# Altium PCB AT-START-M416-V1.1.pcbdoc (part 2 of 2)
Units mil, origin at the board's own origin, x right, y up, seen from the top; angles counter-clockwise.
Board outline 4292.45 x 3617.4 mil, 2 copper layers (Top Layer, Bottom Layer); 119 components, 108 nets, 464 pads, 671 vias.
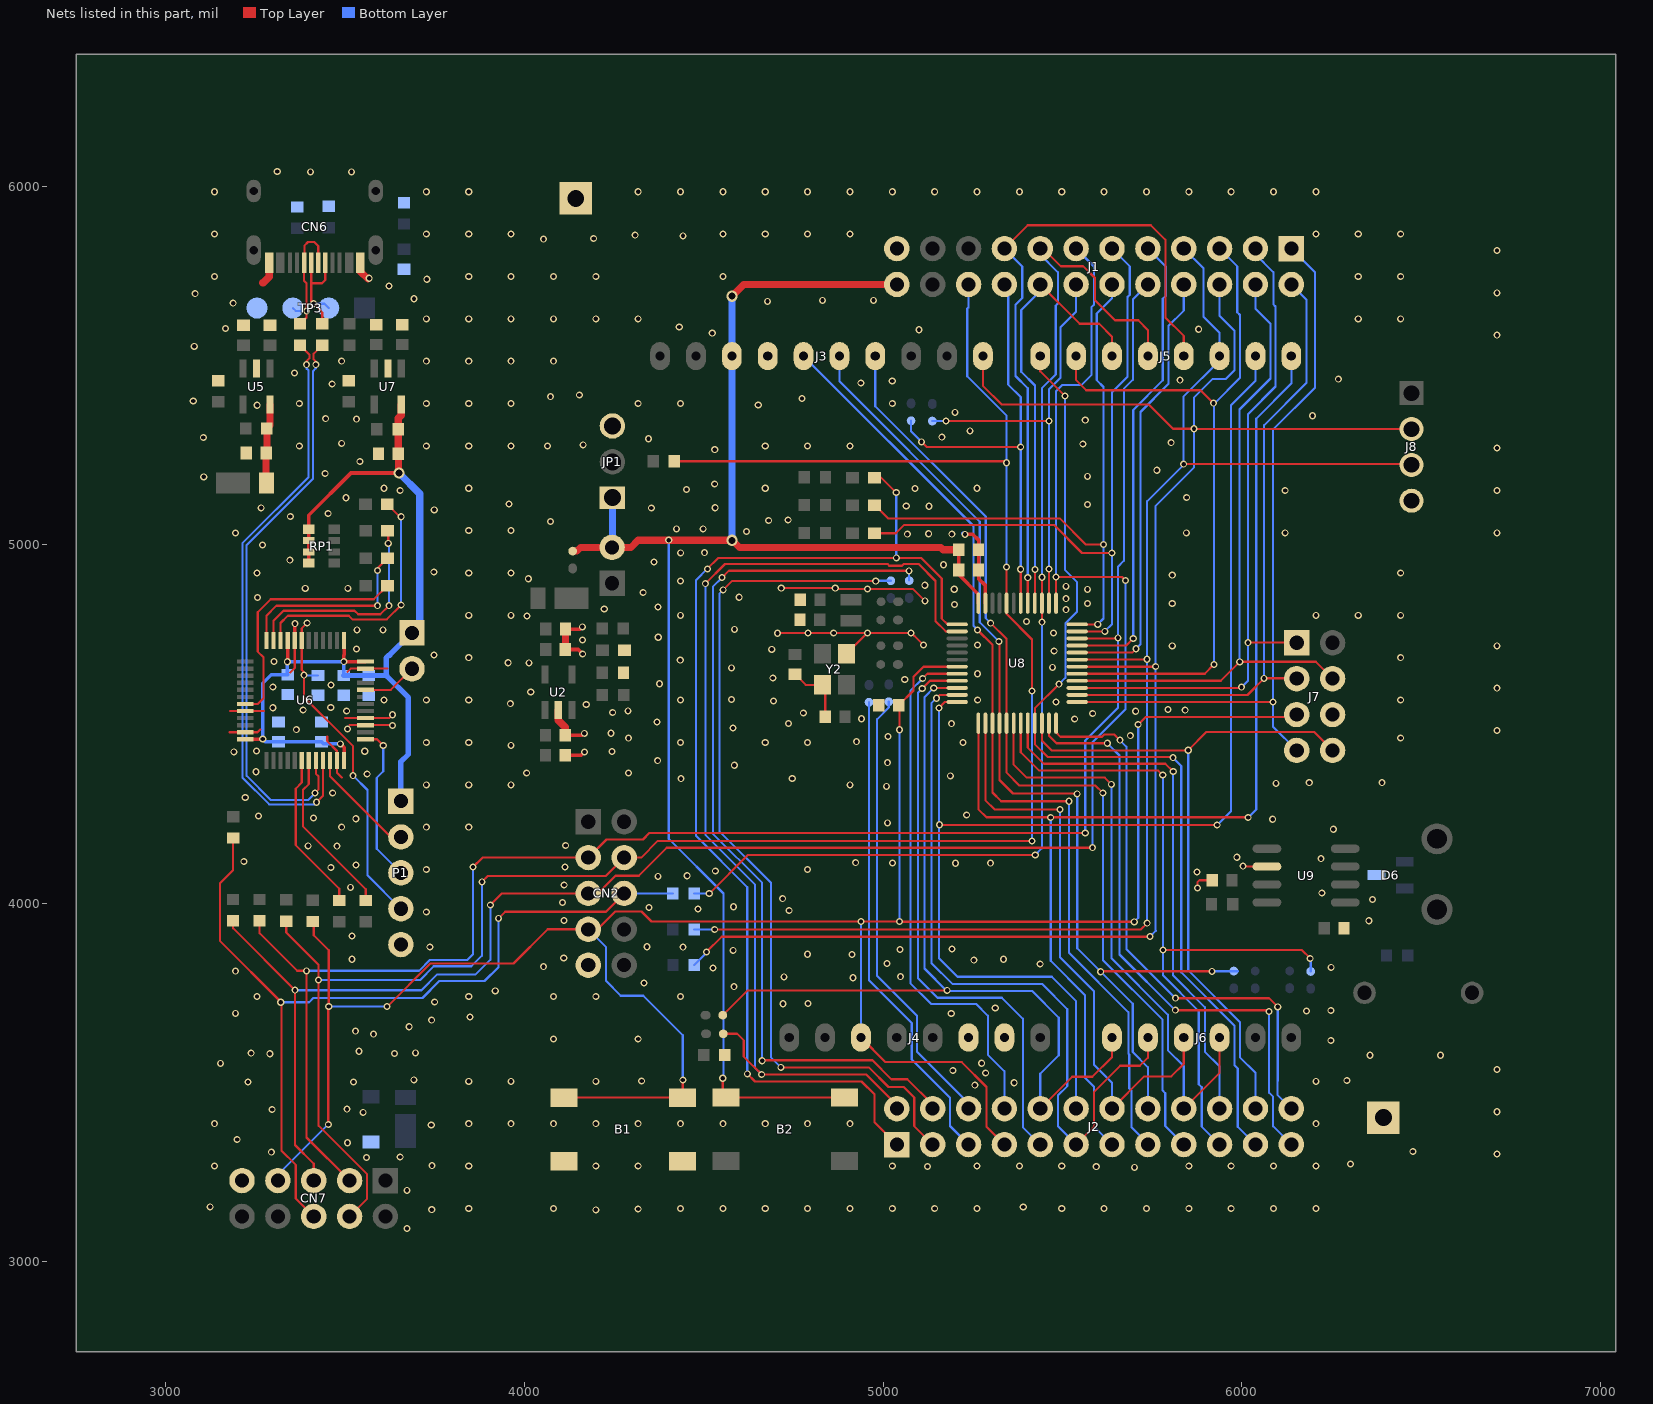
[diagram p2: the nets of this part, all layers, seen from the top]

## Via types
v1: diameter 19.68, hole 11.81, Top Layer to Bottom Layer, 317 vias
v2: diameter 19.7, hole 11.81, Top Layer to Bottom Layer, 224 vias
v3: diameter 19.7, hole 11.8, Top Layer to Bottom Layer, 111 vias
v4: diameter 31.5, hole 19.68, Top Layer to Bottom Layer, 19 vias

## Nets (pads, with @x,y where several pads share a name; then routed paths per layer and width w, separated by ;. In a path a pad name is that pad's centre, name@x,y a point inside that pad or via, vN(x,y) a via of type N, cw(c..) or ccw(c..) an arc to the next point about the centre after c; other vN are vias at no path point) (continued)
GND: B1.3 B1.4 C1.1 C2.1 C3.1 C4.1 C5.1 C6.1 C7.1 C8.1 C9.1 C10.1 C11.1 C12.1 C13.1 C14.1 C15.1 C16.1 C17.1 C18.1 C19.1 C20.1 C21.1 C22.1 C23.2 C24.2 C25.2 C26.2 CN2.9 CN6.A1B12 CN6.B1A12 CN7.9 D4.2 D6.3 J1.23 J3.7 J4.6 J4.7 J7.6 J8.4 JP1.3 LED1.2 P1.5 R2.2 R20.2 R34.2 R35.2 R36.2 R49.2 R51.2 T1.1 T2.1 TP3.4 U2.2 U5.2 U6.8 U6.20 U6.23 U6.35 U6.39 U6.40 U6.47 U7.2 U8.47 U9.2 Y2.2 Y2.4 | length 2758.9
  Top Layer w6: 3177.08,4477.12 U6.23@3221.25,4477.12 3255.17,4477.12 3262.81,4484.75 ; 3178.66,4536.18 U6.20@3221.25,4536.18 3273.47,4536.18 ; 3346.33,4643.65 3359.04,4656.36 U6.8@3359.04,4733.03 ; 3449.63,4465.2 3449.63,4452.3 3477.16,4424.78 U6.35@3477.16,4398.38 3477.16,4363.64 3490.18,4350.62 ; 3500.02,4516.49 U6.40@3555.9,4516.49 3622.6,4516.49 v1(3631.92,4525.82) ; 3506.46,4645.8 3514.94,4654.29 U6.47@3555.9,4654.29 3617.03,4654.29 ; 3512.29,4496.81 U6.39@3555.9,4496.81 3630.94,4496.81 v2(3631.92,4495.82) ; v3(4705.25,4753.04) 4705.97,4753.76 v3(4790.18,4753.76) v3(4861.89,4753.76) v2@4955.4,4753.76 ; v3(4715.75,4878.79) v3(4866.25,4878.79) 4868.88,4876.16 v3(4956.33,4876.16) 5083.47,4876.16 v3(5116.22,4843.4) ; C3.1@4753.97,4638.93 4783.72,4609.18 Y2.4@4830.51,4609.18 4838.41,4601.27 C4.1@4838.41,4520.49 ; Y2.2@4897.44,4695.8 v2@4955.4,4753.76 ; v3(5112.65,4719.92) 5086.5,4746.07 5086.5,4746.49 5079.23,4753.76 v3(5077.77,4753.76) v2(4956.43,4753.76) v2@4955.4,4753.76 ; v3(5875.97,4042.49) 5875.97,4058.49 5881.97,4064.49 C13.1@5917.41,4064.49 ; v3(6002.97,4103.49) 6003.97,4102.49 U9.2@6069.82,4102.49
  Top Layer w10: U6.8@3359.04,4733.03 3359.04,4778.94 v2(3359.92,4779.82) ; C23.2@4113.53,4412.49 4157.32,4412.49 v3(4167.06,4422.23) ; C24.2@4113.53,4468.49 4161.11,4468.49 v3(4166.69,4474.06) ; C25.2@4113.81,4707.66 4149.5,4707.66 v3(4162.07,4695.08) ; C26.2@4114.14,4764.74 4154.85,4764.74 v1(4161.02,4770.91) ; v1(5227.81,5028.9) 5249.82,5028.9 5265.85,5012.87 C6.1@5265.85,4985.83 C7.1@5265.85,4929.3 ; C7.1@5265.91,4929.24 5265.91,4905.39 5284.94,4886.36 U8.47@5284.94,4836.89
  Top Layer w20: 3269.89,5730.23 3271.47,5730.23 3288.12,5746.88 CN6.B1A12@3288.12,5785.52 ; CN6.A1B12@3541.92,5785.52 3541.92,5761.94 v2@3563.18,5740.69 ; U2.2@4094,4538.45 4094,4510.46 4113.53,4490.93 C24.2@4113.53,4468.49 ; C25.2@4113.81,4707.66 4114.14,4707.99 C26.2@4114.14,4764.74
  Bottom Layer w10: v1@5221.26,5032.4 5224.76,5028.9 v1(5227.81,5028.9)
  other v1: 4198.61,3145.4 3741.26,3145.84 4316.72,3147.4 3844.28,3149.4 4080.5,3149.4 4434.83,3149.4 4552.94,3149.4 4671.05,3149.4 4789.16,3149.4 4907.27,3149.4 5025.38,3149.4 5143.49,3149.4 5261.6,3149.4 5497.82,3149.4 5615.93,3149.4 5734.04,3149.4 5852.15,3149.4 5970.26,3149.4 6088.37,3149.4 6206.48,3149.4 5390.37,3152.95 3123.38,3153.74 5700.88,3263.95 5123.75,3265.93 5594.02,3265.73 3135.61,3267.51 3742.15,3268.39 3844.28,3267.51 4198.61,3267.51 4316.72,3267.51 5025.38,3267.51 5261.6,3267.51 5379.71,3267.51 5497.82,3267.51 5852.15,3267.51 5970.26,3267.51 6088.37,3267.51 6206.48,3267.51 6302.59,3273.51 6711.39,3300.71 6476.7,3307.73 3739.85,3381.93 3135.61,3385.62 3844.28,3385.62 3962.39,3385.62 4080.5,3385.62 4198.61,3385.62 4316.72,3385.62 4434.83,3385.62 4552.94,3385.62 4671.05,3385.62 4789.16,3385.62 4907.27,3385.62 6206.48,3385.62 6711.39,3418.82 3844.28,3503.73 3962.39,3503.73 4198.61,3503.73 6206.48,3503.73 4326.58,3504.52 6292.62,3505.7 6711.39,3536.93 4080.5,3621.84 4316.72,3621.84 3253.72,3739.95 3844.28,3739.95 4080.5,3739.95 4198.61,3739.95 4434.83,3739.95 5252.72,3841.48 4913.27,3857.06 4789.16,3858.06 3726.16,3976.17 4719.54,4012.9 3726.16,4094.28 4789.16,4094.28 5201.36,4111.78 4923.27,4113.28 3489.94,4212.39 3726.16,4212.39 3844.28,4212.39 3726.16,4330.5 3844.28,4330.5 3962.39,4330.5 4907.27,4330.5 4005.84,4363.65 3962.39,4440.61 3726.16,4448.61 3844.28,4448.61 4434.83,4448.61 4671.05,4448.61 4789.16,4448.61 4925.27,4450.61 6442.7,4461.04 6711.39,4481.81 4939.27,4514.72 4777.16,4530.72 3960.39,4556.72 4694.14,4564.35 3608.05,4566.72 3726.16,4566.72 3844.28,4566.72 4434.83,4566.72 5263.37,4566.72 6442.7,4566.72 4017.17,4589.47 6711.39,4599.92 3954.39,4670.83 4012.13,4670.54 4434.04,4677.99 3844.28,4684.83 6442.7,4684.83 4689.2,4708.25 6711.39,4718.03 5262.78,4720.35 4006.5,4800.94 3844.28,4802.94 3962.39,4802.94 4434.83,4802.94 6206.48,4802.94 6324.59,4802.94 6442.7,4802.94 4330.8,4867 4434.83,4899.05 4010.44,4904.91 3253.72,4921.05 3844.28,4921.05 3962.39,4921.05 6442.7,4921.05 6711.39,5032.99 3844.28,5039.16 3962.39,5039.16 4072.21,5064.82 4353.46,5102.01 4531.49,5103.04 3956.39,5113.27 6711.39,5151.1 3608.05,5157.27 3844.28,5157.27 4671.05,5157.27 5261.6,5157.27 4530.18,5169.4 4530.3,5264.94 6711.39,5269.21 3371.83,5275.38 3726.16,5275.38 3844.28,5275.38 3962.39,5275.38 4063.76,5275.38 4671.05,5275.38 4789.16,5275.38 4907.27,5275.38 4163.35,5278.35 3489.94,5282.48 4345.54,5295.42 3254.32,5388.75 4651.51,5389.35 3371.83,5393.49 3726.16,5393.49 3844.28,5393.49 3962.39,5393.49 4316.72,5393.49 4434.83,5393.49 5025.38,5393.49 4773.37,5407.31 4072.3,5412.62 4152.61,5417.49 3489.94,5511.6 3726.16,5511.6 3844.28,5511.6 3962.39,5511.6 4080.5,5511.6 6711.39,5584.17 5879.58,5600.63 3726.16,5629.71 3844.28,5629.71 3962.39,5629.71 4080.5,5629.71 4198.61,5629.71 4316.72,5629.71 6324.59,5629.71 6442.7,5629.71 6711.39,5702.28 3621.67,5721.18 3727.35,5740.12 3135.61,5747.82 3844.28,5747.82 3962.39,5747.82 4080.5,5747.82 4198.61,5747.82 4552.94,5747.82 6324.59,5747.82 6442.7,5747.82 6711.39,5820.39 4052.5,5851.93 4192.61,5853.93 4441.93,5861.19 4308.43,5862.97 3135.61,5865.93 3726.16,5865.93 3844.28,5865.93 3962.39,5865.93 4552.94,5865.93 4671.05,5865.93 4789.16,5865.93 4907.27,5865.93 6206.48,5865.93 6324.59,5865.93 6442.7,5865.93 3135.61,5984.04 3726.16,5984.04 3844.28,5984.04 4316.72,5984.04 4434.83,5984.04 4552.94,5984.04 4671.05,5984.04 4789.16,5984.04 4907.27,5984.04 5025.38,5984.04 5143.49,5984.04 5261.6,5984.04 5379.71,5984.04 5497.82,5984.04 5615.93,5984.04 5734.04,5984.04 5852.15,5984.04 5970.26,5984.04 6088.37,5984.04 6206.48,5984.04 3310.43,6040.29
  other v2: 3672.2,3093.06 3672.47,3199.71 3559.16,3291.61 3653.25,3292.5 3294,3306.17 3506.02,3332.5 3198.63,3341.75 3549.87,3417.35 3296.17,3424.98 3504.98,3426.15 5255.54,3492.87 5365.15,3499.68 3228.92,3501.56 3522.79,3502.15 3691.11,3507.76 5285.68,3526.79 5194.13,3533.53 3152.29,3553.86 5274.63,3554.03 3289.67,3580.56 3637.43,3581.44 3237.63,3582.27 3695.65,3583.12 3538.06,3587.46 3579,3635.21 3528.58,3643.52 3678.17,3655.78 3740.98,3674.21 3847.64,3682.95 3193.72,3693.28 5189.63,3693.14 6180.37,3699.72 5312.46,3708.2 4720.65,3720.04 4790.52,3720.83 3749.27,3724.53 3918.19,3755.95 4583.61,3767.53 4333.11,3777.55 4915.63,3792.43 4723.47,3794.94 5048.18,3795.59 3193.72,3810.91 4525.54,3819.39 4052.83,3823.31 5437.72,3831.13 5010.5,3831.88 3518.6,3843.99 5335.62,3844.03 4109.25,3847.81 4581.64,3868.98 5046.99,3871.38 5192.13,3872.51 3735.9,3878.03 4441.86,3877.81 4341.2,3878.99 3518.6,3908.73 4110.1,3952.22 4737.82,3979.9 4483.25,3984.34 4346.94,3988.33 4582.48,3990.46 4105.76,4002.54 3514.75,4044.56 4110.5,4051.1 4371.83,4075.17 4453.27,4076.83 3459.69,4100.22 4112.47,4101.49 3530.14,4106.73 5298.87,4111.95 5025.57,4112.54 3217.09,4116.59 3476.86,4159.43 3396.66,4160.28 4114.58,4161.55 5012.13,4224.55 3529.45,4235.76 3411.13,4237.59 3258.15,4243.3 5232.69,4246.05 3221.2,4294.8 3464.92,4307.4 5009.17,4326.33 4436.21,4347.54 4746.34,4348.33 5187.1,4355.59 3561.25,4360.89 4290.08,4363.66 3250.89,4366.78 4584.77,4384.96 5012.13,4392.23 4371.1,4397.79 3189.36,4422.53 4243.9,4423.16 3252.21,4424.41 3554.4,4424.05 5222.78,4448.25 4290.08,4460.46 5013.36,4465.06 4240.99,4474.13 3363.6,4484.14 3506.08,4485.92 4580.92,4488.88 4736.02,4501.09 5190.21,4500.95 4368.88,4505.26 5533.86,4514.14 4245.68,4532.4 3503.93,4536.25 4288.31,4536.84 3382.58,4538.96 3297.98,4545.23 3459.5,4545.96 5481.39,4561.32 4577.32,4568.11 3297.98,4602.86 3460.17,4608.96 5060.02,4624.06 4692.19,4628.23 5262.89,4640.19 4577.32,4656.53 5471.9,4658.08 3301.33,4674.5 3747.34,4692.23 5476.62,4703.31 3531.17,4708.99 5475.08,4753.94 3532.55,4762.54 3605.58,4762.54 4585.36,4763.88 5399.37,4785.55 5509.36,4818.8 4372.15,4826.17 5509.36,4849.33 3255.26,4853.03 4598.39,4853.48 3388.48,4878.29 3507.29,4878.29 5509.36,4883.96 5116,4886.84 3746.99,4923.79 4360.86,4951.45 3345.43,4956.68 4435.35,4977.17 4501.58,4977.61 3269.05,4998.99 5067.13,5029.27 5191.32,5029.18 5126.72,5030.39 3193.78,5032.65 4680.74,5067.25 4734.94,5069.09 3346.84,5078.63 3452.5,5086.71 3748.16,5097.17 3265.53,5102.71 5127.86,5107.09 5064.31,5107.88 3501.75,5130.86 3653.09,5151.06 5088.78,5156.83 3105.54,5189.16 3444.04,5198.34 3540.75,5231.89 5556.58,5280.86 3104.35,5298.69 5163.46,5299.75 5241.76,5317.4 5563.37,5347.09 3531.67,5349.91 3445.37,5351.39 5200.15,5369.08 3076.24,5400.27 3463.63,5447.81 4937.6,5451.15 5025.23,5456.48 5827.27,5458.64 3358.24,5478.4 3079,5553.13 4523.34,5589.82 5099.47,5599.34 3166.21,5602.49 4431.37,5606.79 3187.53,5673.41 4677.34,5678.58 4830.99,5681.25 4973.09,5681.25 3692.06,5685.72 3081.44,5699.89 3566.6,5742.92 3403.39,6039.7 3517.08,6039.7
  other v3: 6357.06,3576.3 6553.91,3576.3 6247.97,3617.49 6247.97,3701.49 6248.97,3821.49 6353.97,3951.49 6363.97,4010.49 6222.97,4028.49 5874.97,4087.49 4531.97,4090.49 6220.97,4124.49 5985.97,4128.49 6254.97,4206.49 6085.97,4234.49 6094.97,4334.49 6187.97,4336.49 6390.97,4336.49 5688.97,4467.49 5583.97,4529.49 5703.97,4535.49 5841.97,4538.49 5793.97,4540.49 4171.97,4554.49 4376.06,4612.31 5805.88,4718.03 4161.47,4734.22 4372.65,4741.91 4222.15,4820.86 5198.71,4833.39 5569.66,4836.14 5805.88,4836.14 5198.1,4875.69 5569.66,4875.51 5805.88,4914.88 5167.89,4943.97 5845.25,5032.99 6120.84,5032.99 4619.09,5036.42 4423.91,5044.31 4498.08,5044.31 5569.66,5111.73 5846.11,5131.39 6120.84,5151.1 4451.46,5153.83 5569.66,5190.47 5762.97,5207.49 5802.97,5284.49 6196.97,5359.49 6268.97,5461.49
LD1: LD1.2 U6.10 | length 713.3
  Top Layer w6: U6.10@3319.67,4733.03 3319.67,4781.57 3339.92,4801.82 3509.92,4801.82 3519.92,4791.82 3615.92,4791.82 v1(3655.92,4831.82) ; LD1.2@3617.1,5113.03 3652.31,5077.82 v1(3655.92,5077.82)
  Bottom Layer w6: v1(3655.92,4831.82) v1(3655.92,5077.82)
LD2: LD2.2 U6.11 | length 613.2
  Top Layer w6: U6.11@3299.99,4733.03 3299.99,4787.88 3327.92,4815.82 3525.92,4815.82 3535.92,4805.82 3597.92,4805.82 v1(3621.92,4829.82) ; LD2.2@3618.06,5038.93 3619.92,5037.06 v1(3619.92,5003.82)
  Bottom Layer w6: v1(3619.92,5003.82) 3621.92,5001.82 v1(3621.92,4829.82)
LD3: LD3.2 U6.12 | length 534.1
  Top Layer w6: U6.12@3280.3,4733.03 3280.3,4802.2 3307.92,4829.82 v1(3589.92,4829.82) ; v1(3589.92,4927.82) 3589.92,4933.85 LD3.2@3618.1,4962.03
  Bottom Layer w6: v1(3589.92,4829.82) v1(3589.92,4927.82)
LD4: LD4.2 U6.19 | length 696.8
  Top Layer w6: U6.19@3221.25,4555.86 3255.97,4555.86 3271.92,4571.82 3271.92,4685.82 3255.92,4701.82 3255.92,4811.82 3291.92,4847.82 3579.85,4847.82 LD4.2@3618.06,4886.03
M-ATLK_RX: R48.1 U6.31 | length 470.7
  Top Layer w6: U6.31@3398.41,4398.38 3398.41,4332.34 3381.92,4315.85 3381.92,4214.86 3557.1,4039.68 R48.1@3557.1,4007.03
M-ATLK_TX: R47.1 U6.30 | length 448.5
  Top Layer w6: U6.30@3378.73,4398.38 3378.73,4336.66 3361.92,4319.85 3361.92,4162.2 3483.1,4041.03 R47.1@3483.1,4007.03
M-BOOT0: J9.2 U6.44 | length 154.6
  Top Layer w6: U6.44@3555.9,4595.23 3627.3,4595.23 J9.2@3686.1,4654.03
M-NRST: C22.2 P1.4 U6.7 | length 957
  Top Layer w6: v1(3393.92,4781.82) 3378.73,4766.62 U6.7@3378.73,4733.03 3378.73,4651.01 3384.73,4645.01 3384.73,4575.37 3521.92,4438.17 v1(3521.92,4355.82)
  Bottom Layer w6: v2(3384.73,4636.07) 3385.42,4635.38 C22.2@3423.92,4635.38 ; v1(3521.92,4355.82) 3561.92,4315.82 3561.92,4078.2 P1.4@3655.1,3985.03
M-SWCLK: P1.3 U6.37 | length 447.4
  Top Layer w6: U6.37@3555.9,4457.43 3588.31,4457.43 v1(3605.92,4439.82)
  Bottom Layer w6: v1(3605.92,4439.82) 3605.92,4367.82 3587.92,4349.82 3587.92,4152.2 P1.3@3655.1,4085.03
M-SWDIO: P1.2 U6.34 | length 311.8
  Top Layer w6: U6.34@3457.47,4398.38 3457.47,4354.27 3626.72,4185.03 P1.2@3655.1,4185.03
M-USB_DM: R38.2 U6.32 | length 1617.9
  Top Layer w6: v2(3415.92,4307.82) 3425.78,4317.68 3425.78,4353.69 3418.1,4361.38 U6.32@3418.1,4398.38 ; v2(3417.92,5501.82) 3417.92,5510.87 3411.92,5516.87 3411.92,5532.16 R38.2@3435.92,5556.16
  Bottom Layer w6: v2(3415.92,4307.82) 3395.92,4287.82 3292.9,4287.82 3225.1,4355.61 3225.1,4998.99 3409.92,5183.82 3409.92,5483.82 3417.92,5491.82 v2(3417.92,5501.82)
M-USB_DP: R37.2 U6.33 | length 1662.9
  Top Layer w6: R37.2@3373.92,5556.16 3399.92,5530.16 3399.92,5519.55 3391.92,5511.55 v1(3391.92,5501.82) ; v2(3419.92,4281.82) 3437.78,4299.68 U6.33@3437.78,4398.38
  Bottom Layer w6: v1(3391.92,5501.82) 3391.92,5491.42 3397.92,5485.42 3397.92,5188.79 3213.1,5003.96 3213.1,4350.64 3287.92,4275.82 3413.92,4275.82 v2(3419.92,4281.82)
NRST/PF2: B1.1 B1.2 C5.2 CN2.7 CN7.7 J2.7 J4.3 J7.5 R46.2 U8.7 | length 6865.4
  Top Layer w6: R46.2@3409.1,3947.03 3412.1,3944.03 3412.1,3911.15 3453.92,3869.33 v2(3453.92,3712.19) 3452.74,3711.01 v2(3452.74,3383.56) ; v1(3616.76,3711.99) 3737.05,3832.28 3969.28,3832.28 4064.53,3927.53 CN2.7@4177.67,3927.53 4203.13,3927.53 4252.77,3977.17 4326.06,3977.17 4353.93,3949.29 v1@4938.05,3949.29 ; B1.1@4110.01,3458.22 B1.2@4440.71,3458.22 4441.21,3458.72 v3(4441.21,3507.15) ; J4.3@4937.93,3625.82 5006.53,3557.21 5218.78,3557.21 5287.94,3488.05 5287.94,3377.38 J2.7@5337.93,3327.39 ; v1(4937.93,3949.17) v1@4938.05,3949.29 ; v3(5045.56,4484.05) 5045.56,4549.51 C5.2@5043.05,4552.03 5084.66,4593.63 5084.66,4632.06 5112.4,4659.79 U8.7@5206.24,4659.79 ; v3(5699.97,3948.49) 5046.42,3948.49 v3(5045.61,3949.29) v1@4938.05,3949.29 ; v3(5710.97,4498.49) 5731.97,4519.49 6146.02,4519.49 J7.5@6152.93,4526.39
  Bottom Layer w6: CN7.7@3312.1,3227.03 3312.1,3242.91 v2(3452.74,3383.56) ; v2(3453.92,3712.19) 3616.56,3712.19 v1(3616.76,3711.99) ; CN2.7@4177.67,3927.53 4227.41,3877.79 4227.41,3783.2 4268.13,3742.48 4330.94,3742.48 4441.21,3632.2 v3(4441.21,3507.15) ; J4.3@4937.93,3625.82 v1(4937.93,3949.17) ; v3(5045.61,3949.29) v3(5045.56,4484.05) ; v3(5699.97,3948.49) 5710.97,3959.49 v3(5710.97,4498.49)
PA0: J2.10 J6.1 R18.1 U8.10 | length 2535.9
  Top Layer w6: R18.1@4552.67,3688.08 4621.93,3757.34 v3(5178.41,3757.34) ; v1(5140.91,4600.69) U8.10@5206.24,4600.69 ; J2.10@5437.93,3427.39 5526.91,3516.37 5583.1,3516.37 5637.93,3571.19 J6.1@5637.93,3625.82
  Bottom Layer w6: v1(5140.91,4600.69) 5114.9,4574.68 5114.9,3818.16 5178.05,3755.01 v3@5178.41,3755.38 ; v3(5178.41,3757.34) v3@5178.41,3755.38 ; J2.10@5437.93,3427.39 5437.93,3524.74 5489.42,3576.23 5489.42,3681.18 5415.22,3755.38 v3@5178.41,3755.38
PA1: J2.11 J6.2 U8.11 | length 2060.1
  Top Layer w6: v1(5148.24,4571.84) 5157.39,4580.99 U8.11@5206.24,4580.99 ; J2.11@5537.93,3327.39 5587.23,3376.7 5587.23,3473.4 5660.76,3546.92 5715.38,3546.92 5737.93,3569.46 J6.2@5737.93,3625.82
  Bottom Layer w6: v1(5148.24,4571.84) 5134.38,4557.98 5134.38,3833.78 5192.69,3775.48 5442.56,3775.48 5513.01,3705.02 5513.01,3490.3 5487.21,3464.5 5487.21,3378.11 J2.11@5537.93,3327.39
PA2: J2.12 J5.2 U8.12 | length 3617.3
  Top Layer w6: v1(5155.54,4544.83) 5172,4561.29 U8.12@5206.24,4561.29 ; v1(5156.64,4219.06) 5157.26,4218.43 v1(5931.14,4218.43)
  Bottom Layer w6: v1(5155.54,4544.83) v1@5155.54,4216.06 ; v1(5156.64,4219.06) 5156.64,4217.16 v1@5155.54,4216.06 ; J2.12@5537.93,3427.39 5537.93,3727.28 5470.06,3795.15 5207.02,3795.15 5155.54,3846.64 v1@5155.54,4216.06 ; v1(5931.14,4218.43) 5970.01,4257.3 5970.01,5389.55 6037.93,5457.47 J5.2@6037.93,5525.82
PA3: J2.13 J5.1 U8.13 | length 3322.2
  Top Layer w6: U8.13@5265.24,4502.29 5265.24,4262.51 5287.79,4239.96 5467.18,4239.96 5466.97,4239.76 v3(5466.97,4239.49) 5467.45,4239.96 6016.73,4239.96 v1(6017.57,4239.12)
  Bottom Layer w6: v3(5466.97,4239.49) 5466.97,3839.49 5562.47,3743.99 5562.47,3513.58 5588.15,3487.9 5588.15,3377.18 J2.13@5637.93,3327.39 ; v1(6017.57,4239.12) 6040.14,4261.69 6040.14,5351.42 6137.93,5449.2 J5.1@6137.93,5525.82
PA4: J2.14 J6.3 U8.14 | length 1653.3
  Top Layer w6: U8.14@5284.94,4502.29 5284.94,4287.26 5310.73,4261.47 v3(5492.97,4261.49) ; J2.14@5637.93,3427.39 5727.92,3517.39 5803.28,3517.39 5837.93,3552.03 J6.3@5837.93,3625.82
  Bottom Layer w6: v3(5492.97,4261.49) 5492.97,3849.49 5587.68,3754.78 5587.68,3549.98 5637.93,3499.74 J2.14@5637.93,3427.39
PA5: J2.15 J3.6 U8.15 | length 2706.5
  Top Layer w6: v1(5262.99,4762.21) 5304.64,4720.55 U8.15@5304.64,4502.29 5304.64,4309.03 5329.11,4284.57 v1(5517.68,4284.57)
  Bottom Layer w6: J3.6@4777.93,5525.82 5251.54,5052.21 5251.54,4773.66 v1(5262.99,4762.21) ; v1(5517.68,4284.57) 5517.97,4284.27 5517.97,3861.78 5683.62,3696.13 5683.62,3580.61 5686.12,3578.1 5686.12,3483.5 5692.43,3477.2 5692.43,3375.89 5737.93,3330.39 J2.15@5737.93,3327.39
PA6: J2.16 J3.5 R25.1 U8.16 | length 2941.9
  Top Layer w6: v1(5322.25,4730.35) 5324.34,4728.26 U8.16@5324.34,4502.29 5324.34,4343.73 5361.93,4306.14 5540.09,4306.14 v1(5540.82,4305.41) ; v3(5606.26,3809.24) 5607.43,3810.42 v3(5916.99,3810.42)
  Bottom Layer w6: J3.5@4877.93,5525.82 4877.93,5455.38 5268.99,5064.32 5268.99,4783.61 v1(5322.25,4730.35) ; v1(5540.82,4305.41) 5540.82,3874.69 v3(5606.26,3809.24) 5695.62,3719.89 5695.62,3585.58 5737.93,3543.27 J2.16@5737.93,3427.39 ; v3(5916.99,3810.42) 5988.44,3810.42 R25.1@5988.61,3810.24
PA7: J2.17 J3.4 U8.17 | length 2678.8
  Top Layer w6: v1(5299.64,4781.17) 5344.04,4736.77 U8.17@5344.04,4502.29 5344.04,4364.42 5379.71,4328.75 5591.63,4328.75 v1(5612.44,4307.94)
  Bottom Layer w6: J3.4@4977.93,5525.82 4977.93,5386.12 5285.71,5078.34 5285.71,4795.1 v1(5299.64,4781.17) ; v1(5612.44,4307.94) 5612.44,3842.02 5778.99,3675.47 5778.99,3478.08 5786.43,3470.64 5786.43,3378.89 J2.17@5837.93,3327.39
PA8: J1.5 J5.7 U8.29 | length 2084.6
  Top Layer w6: J5.7@5537.93,5525.82 5537.93,5458.76 5565.91,5430.77 5884.76,5430.77 v3(5921.04,5394.49) ; U8.29@5540.84,4640.09 5896.32,4640.09 v1(5922.04,4665.82)
  Bottom Layer w6: v1(5922.04,4665.82) 5922.04,5393.49 v3(5921.04,5394.49) 5924.08,5394.49 5994.76,5465.17 5994.76,5640.27 5987.32,5647.71 5987.32,5776.08 J1.5@5937.91,5825.49
PA9/USART1_TX: J1.6 J3.1 J8.2 R16.1 U8.30 | length 4798.7
  Top Layer w6: v3(4507.15,3864.57) 4549.44,3906.86 5743.35,3906.86 v3(5743.97,3907.49) ; J3.1@5277.93,5525.82 5277.93,5443.53 5330.97,5390.49 5740.97,5390.49 5808.16,5323.3 v1(5866.24,5323.3) 5867.05,5322.49 J8.2@6473.03,5322.49 ; U8.30@5540.84,4659.79 5759.41,4659.79 v1(5759.65,4660.03)
  Bottom Layer w6: R16.1@4473.12,3828.11 v3@4503.24,3858.23 ; v3(5743.97,3907.49) 5759.65,3923.17 5759.65,3923.81 ; 5759.97,3923.49 5759.65,3923.81 ; J1.6@5937.91,5725.49 5937.91,5637.6 5979.46,5596.05 5979.46,5485.94 5955.89,5462.37 5918.5,5462.37 5866.24,5410.11 v1(5866.24,5323.3) 5866.24,5214.76 5759.65,5108.17 v1(5759.65,4660.03) 5759.65,3923.81
PA10/USART1_RX: J1.7 J5.3 J8.3 R15.1 U8.31 | length 4108.2
  Top Layer w6: v1(4530.17,3927.07) 5718.51,3927.07 v1(5735.99,3944.55) ; U8.31@5540.84,4679.39 5734.69,4679.39 v1(5735.85,4680.55) ; v3(5837.7,5224.5) 6471.01,5224.5 J8.3@6473.03,5222.49
  Bottom Layer w6: R15.1@4472.76,3927.07 v1(4530.17,3927.07) ; v1@5735.97,3944.57 5735.97,4680.42 v1(5735.85,4680.55) 5735.85,5121.36 5837.7,5223.22 v3(5837.7,5224.5) 5837.7,5413.41 5937.93,5513.63 J5.3@5937.93,5525.82 5937.93,5590.27 5893.48,5634.72 5893.48,5769.93 J1.7@5837.91,5825.49
PA11: J1.8 U8.32 | length 1239.2
  Top Layer w6: U8.32@5540.84,4699.09 5694.09,4699.09 v1(5704.78,4709.78)
  Bottom Layer w6: v1(5704.78,4709.78) 5717.32,4722.32 5717.32,5370.14 5795.04,5447.87 5795.04,5609.74 5837.91,5652.61 J1.8@5837.91,5725.49
PA12: J1.9 U8.33 | length 1309.7
  Top Layer w6: U8.33@5540.84,4718.79 5677.35,4718.79 v1(5697.23,4738.67)
  Bottom Layer w6: v1@5697.29,4738.73 5696.97,4739.04 5696.97,5375.47 5779.51,5458 5779.51,5685.69 5787.67,5693.85 5787.67,5775.73 J1.9@5737.91,5825.49
PA13/SWDIO: CN2.3 CN7.3 J1.10 R44.2 U8.34 | length 5032.7
  Top Layer w6: R44.2@3261.3,3951.41 3261.3,3916.44 3365.92,3811.82 v2(3391.92,3811.82) 3391.92,3347.2 CN7.3@3512.1,3227.03 ; v2(3856.23,4101.13) 3882.63,4127.53 CN2.3@4177.67,4127.53 4228.3,4178.15 4330.17,4178.15 4348.4,4196.38 v1(5563.32,4196.38) ; U8.34@5540.84,4738.49 5652.8,4738.49 v1(5654.64,4740.33)
  Bottom Layer w6: v2(3391.92,3811.82) 3705.89,3811.82 3735.97,3841.9 3840.32,3841.9 3856.23,3857.81 v2(3856.23,4101.13) ; v1(5563.32,4196.38) 5563.32,4453.84 5654.64,4545.15 v1(5654.64,4740.33) ; v1@5654.58,4740.38 5654.58,4938.43 5670.97,4954.82 5670.97,5434.49 5696.16,5459.68 5696.16,5683.74 J1.10@5737.91,5725.49
PA14/SWCLK: CN2.5 CN7.5 J1.13 R41.2 U8.37 | length 5360.3
  Top Layer w6: R41.2@3187.3,3951.41 3187.3,3930.44 v2(3359.92,3757.82) 3359.92,3326.08 3412.1,3273.9 CN7.5@3412.1,3227.03 ; v2(3904.53,3995.38) 3936.68,4027.53 CN2.5@4177.67,4027.53 4204.22,4027.53 4253.74,4077.05 4318.57,4077.05 4396.59,4155.07 v1@5583.61,4155.07 ; U8.37@5481.84,4836.89 v1(5481.84,4909.82) 5665.77,4909.82 v1(5675.67,4899.91)
  Bottom Layer w6: v2(3359.92,3757.82) 3712.75,3757.82 3756.74,3801.81 3863.54,3801.81 3904.53,3842.8 v2(3904.53,3995.38) ; v1(5481.84,4909.82) 5481.84,5427.57 5499.95,5445.69 5553.32,5445.69 5580.44,5472.8 5580.44,5661.67 5587.65,5668.88 5587.65,5775.76 J1.13@5537.91,5825.49 ; v1(5583.61,4155.05) 5583.61,4449.12 5675.67,4541.19 v1(5675.67,4899.91)
PA15: J1.14 R29.1 U8.38 | length 1245.1
  Top Layer w6: v1(5174.93,5344.52) v1(5462.07,5344.52) ; U8.38@5462.14,4836.89 v1(5462.14,4932.14)
  Bottom Layer w6: R29.1@5136.87,5344.52 v1(5174.93,5344.52) ; v1(5462.14,4932.14) v1(5462.07,5344.52) ; v1@5462.14,5344.59 5462.14,5433.06 5494.14,5465.06 5494.14,5606.27 5537.91,5650.04 J1.14@5537.91,5725.49
PB0: J2.18 J6.4 U8.18 | length 1638.5
  Top Layer w6: U8.18@5363.74,4502.29 5363.74,4386.84 5400.09,4350.49 5617.48,4350.49 v1(5636.13,4331.89) ; J2.18@5837.93,3427.39 5937.93,3527.39 J6.4@5937.93,3625.82
  Bottom Layer w6: v1(5636.13,4331.89) 5636.13,3847.33 5793.76,3689.7 5793.76,3590.68 5837.93,3546.51 J2.18@5837.93,3427.39
PB1: J2.19 R27.1 U8.19 | length 2056.4
  Top Layer w6: U8.19@5383.34,4502.29 5383.34,4421.23 5434.64,4369.93 5766.96,4369.93 v1(5779.45,4357.43) ; v3(5779.97,3869.49) 6167.48,3869.49 v3(6190.55,3846.41)
  Bottom Layer w6: v1(5779.45,4357.43) 5779.97,4356.92 v3(5779.97,3869.49) 5779.97,3799.49 5879.97,3699.49 5879.97,3495.49 5887.97,3487.49 5887.97,3377.35 J2.19@5937.93,3327.39 ; v3(6190.55,3846.41) 6192.02,3844.94 R27.1@6192.02,3810.08
PB2: J2.20 U8.20 | length 1495.5
  Top Layer w6: U8.20@5403.04,4502.29 5403.04,4434.24 5447.99,4389.29 5786.72,4389.29 v1(5808.67,4367.33)
  Bottom Layer w6: v1(5808.67,4367.33) 5807.97,4366.63 5807.97,3799.49 5896.97,3710.49 5896.97,3586.12 5937.93,3545.16 J2.20@5937.93,3427.39
PB3: J1.15 J5.5 R14.1 U8.39 | length 3236
  Top Layer w6: v3(4514.86,4027.13) 4622.69,4134.96 v3(5423.96,4134.96) ; J1.15@5437.91,5825.49 5446.38,5825.49 5495.43,5776.43 5557.4,5776.43 5590.45,5743.38 5590.45,5681.42 5646.22,5625.64 5710.95,5625.64 5737.93,5598.66 J5.5@5737.93,5525.82 ; v1(5442.44,4784.01) U8.39@5442.44,4836.89 v1(5442.44,4909.13)
  Bottom Layer w6: R14.1@4472.73,4026.98 4514.71,4026.98 v3(4514.86,4027.13) ; v3(5423.96,4134.96) 5442.44,4153.44 v1(5442.44,4784.01) ; J1.15@5437.91,5825.49 5437.91,5808.94 5486.88,5759.97 5486.88,5672.32 5480.88,5666.32 5480.88,5474.43 5442.44,5435.99 v1(5442.44,4909.13)
PB4: J1.16 J5.6 U8.40 | length 1240.8
  Top Layer w6: U8.40@5422.74,4836.89 5423.15,4837.3 v1@5423.15,4930.45 ; J1.16@5437.91,5725.49 5547.59,5615.81 5601.93,5615.81 5637.93,5579.82 J5.6@5637.93,5525.82
  Bottom Layer w6: v1(5423.16,4930.46) 5423.16,5444 5385.07,5482.09 5385.07,5654.4 5437.91,5707.24 J1.16@5437.91,5725.49
PB5: J1.17 J5.4 U8.41 | length 1869.6
  Top Layer w6: J1.17@5337.91,5825.49 5403.07,5890.65 5746.37,5890.65 5786.65,5850.37 5786.65,5633.49 5837.93,5582.21 J5.4@5837.93,5525.82 ; U8.41@5403.04,4836.89 v1(5403.03,4907.98)
  Bottom Layer w6: J1.17@5337.91,5825.49 5387.86,5775.54 5387.86,5687.67 5368.76,5668.56 5368.76,5470.53 5403.03,5436.26 v1(5403.03,4907.98)
PB6: J1.18 R28.1 U8.42 | length 1261
  Top Layer w6: v1(5106.66,5286.81) 5121.14,5272.33 v3(5383.33,5272.33) ; U8.42@5383.34,4836.89 v1(5383.33,4931.47)
  Bottom Layer w6: R28.1@5077.61,5345.73 5077.61,5315.86 v1(5106.66,5286.81) ; J1.18@5337.91,5725.49 5348.6,5714.8 5348.6,5446.31 5383.33,5411.58 v3(5383.33,5272.33) v1(5383.33,4931.47)
PB10: J2.21 J5.8 U8.21 | length 2747.7
  Top Layer w6: J5.8@5437.93,5525.82 5437.93,5483.4 v1(5507.1,5414.23) ; v1(5490.29,4611.12) 5422.74,4543.58 U8.21@5422.74,4502.29 5422.74,4443.53 5458.51,4407.76 5806.04,4407.76 v1(5807.81,4405.99)
  Bottom Layer w6: v1(5490.29,4611.12) 5507.87,4628.69 5507.87,4780.3 5539.97,4812.41 5539.97,4896.25 5507.1,4929.13 v1(5507.1,5414.23) ; v1(5807.81,4405.99) 5830.97,4382.83 5830.97,3807.49 5979.61,3658.85 5979.61,3548.48 5988.43,3539.67 5988.43,3376.9 J2.21@6037.93,3327.39
PB11: J2.22 J7.8 U8.22 | length 1990.1
  Top Layer w6: U8.22@5442.44,4502.29 5442.44,4453.78 5470.27,4425.95 5849.6,4425.95 v1(5850.46,4426.81) 5901.14,4477.49 6201.83,4477.49 J7.8@6252.93,4426.39
  Bottom Layer w6: v1(5850.46,4426.81) 5850.46,3813 5994.46,3669 5994.46,3571.01 6037.93,3527.55 J2.22@6037.93,3427.39
PB12: J1.1 J7.7 U8.25 | length 2048.8
  Top Layer w6: U8.25@5540.84,4561.29 6086.53,4561.29 v1(6086.93,4561.69)
  Bottom Layer w6: J1.1@6137.91,5825.49 6203.87,5759.53 6203.87,5437.51 6086.45,5320.09 6086.45,4562.17 v1(6086.93,4561.69) 6086.93,4492.39 J7.7@6152.93,4426.39
PB13: J1.2 J7.3 U8.26 | length 1796.3
  Top Layer w6: U8.26@5540.84,4580.99 6015.59,4580.99 v1(6062.05,4627.46) 6151.86,4627.46 J7.3@6152.93,4626.39
  Bottom Layer w6: v1(6062.05,4627.46) 6062.05,5332.83 6180.29,5451.07 6180.29,5683.11 J1.2@6137.91,5725.49
PB14: J1.3 J7.1 U8.27 | length 1880.4
  Top Layer w6: U8.27@5540.84,4600.69 5996.84,4600.69 v2(5998.91,4602.76) ; v1(6016.96,4726.8) 6152.52,4726.8 J7.1@6152.93,4726.39
  Bottom Layer w6: v2(5998.91,4602.76) 6017.45,4621.3 6017.45,5364.43 6093.97,5440.95 6093.97,5664.24 6087.87,5670.34 6087.87,5759.85 6037.91,5809.81 J1.3@6037.91,5825.49
PB15: J1.4 J7.4 U8.28 | length 1859
  Top Layer w6: U8.28@5540.84,4620.39 5941.08,4620.39 v2(5994.16,4673.47) 6205.85,4673.47 J7.4@6252.93,4626.39
  Bottom Layer w6: v2(5994.16,4673.47) 5993.32,4674.31 5993.32,5377.03 6079.67,5463.37 6079.67,5616.2 6037.91,5657.96 J1.4@6037.91,5725.49
PC13: J2.2 R19.1 U8.2 | length 2908.6
  Top Layer w6: v1(4504.06,4891.23) 4558.87,4946.05 5012.17,4946.05 5016.78,4941.44 5052.48,4941.44 5057.08,4946.05 5098.64,4946.05 5145.95,4898.74 5145.95,4786.73 5174.48,4758.19 U8.2@5206.24,4758.19 ; R19.1@4554.12,3636.15 4592.67,3636.15 4610.95,3617.87 4610.95,3572.61 v3(4661.08,3522.48) 4952.99,3522.48 5037.93,3437.54 J2.2@5037.93,3427.39
  Bottom Layer w6: v1(4504.06,4891.23) 4504.06,4190.77 4642.03,4052.8 4642.03,3541.52 v3(4661.08,3522.48)
PC14: J2.3 R7.1 | length 2444
  Top Layer w6: v1(4553.75,4874.09) 4577.95,4898.29 v1(4979.22,4898.29) ; v3@4714.6,3542.6 4960.01,3542.6 5014.54,3488.07 5056.92,3488.07 5086.53,3458.45 5086.53,3378.79 J2.3@5137.93,3327.39
  Bottom Layer w6: v1(4553.75,4874.09) 4543.09,4863.43 4543.09,4201.14 4687.39,4056.84 4687.39,3569.81 v3(4714.55,3542.65) ; v1(4979.22,4898.29) 4980.24,4899.31 R7.1@5021.33,4899.31
PC15: J2.4 R8.1 | length 2509.9
  Top Layer w6: v3(4550.57,4908.19) 4569.58,4927.2 v3(5071.75,4927.2) ; v3(4662.47,3561.03) 4663.7,3562.26 4969.96,3562.26 5022.73,3509.5 5067.31,3509.5 5137.93,3438.87 J2.4@5137.93,3427.39
  Bottom Layer w6: v3(4550.57,4908.19) 4525.1,4882.71 4525.1,4194.43 4662.47,4057.06 v3(4662.47,3561.03) ; v3(5071.75,4927.2) 5072.35,4926.6 R8.1@5072.35,4899.75
PF0: J2.5 R11.1 | length 1348.3
  Bottom Layer w6: R11.1@4960.34,4560.75 4960.34,3785.54 5079.4,3666.48 5079.4,3564.75 5186.14,3458.01 5186.14,3379.19 J2.5@5237.93,3327.39
PF1: J2.6 R12.1 | length 1253.9
  Bottom Layer w6: R12.1@5015.44,4562.24 5015.44,4546.04 4983,4513.6 4983,3797.51 5094.39,3686.12 5094.39,3585.74 5237.93,3442.21 J2.6@5237.93,3427.39
PF6: J1.11 LED2.2 U8.35 | length 1897.5
  Top Layer w6: LED2.2@4976.02,5031.75 5035.39,5031.75 5058.88,5055.24 5476.03,5055.24 5554.26,4977.01 v1(5637.45,4977.01) ; U8.35@5540.84,4758.19 5540.93,4758.28 v1(5617.84,4758.28)
  Bottom Layer w6: v1(5617.84,4758.28) 5637.91,4778.35 v1@5637.91,4977.01 ; v1(5637.45,4977.01) v1@5637.91,4977.01 ; J1.11@5637.91,5825.49 5687.32,5776.08 5687.32,5696.41 5681.32,5690.41 5681.32,5468.34 5637.91,5424.94 v1@5637.91,4977.01
PF7: J1.12 LED3.2 U8.36 | length 1719.9
  Top Layer w6: LED3.2@4977.17,5109.75 5013.51,5073.41 5491.8,5073.41 5564.57,5000.63 v1(5614.56,5000.63) ; U8.36@5540.84,4777.89 v1(5598.24,4777.89)
  Bottom Layer w6: v1(5598.24,4777.89) 5614.36,4794.01 v1@5614.36,5000.63 ; v1(5614.56,5000.63) v1@5614.36,5000.63 ; J1.12@5637.91,5725.49 5637.91,5687.06 5595.46,5644.61 5595.46,5458.7 5614.36,5439.8 v1@5614.36,5000.63
PF8: J2.1 LED4.2 U8.1 | length 3139
  Top Layer w6: v3(4509.76,4932.49) 4540.22,4962.95 v1@5036.16,4962.95 ; v3(4621.06,3524.68) 4642.55,3503.19 4939.57,3503.19 4975.52,3467.24 4975.52,3389.8 J2.1@5037.93,3327.39 ; LED4.2@4975.17,5193.75 4987.88,5193.75 v1(5036.42,5145.21) ; v1(5036.46,4963.25) v1@5036.16,4962.95 ; U8.1@5206.24,4777.89 5179.04,4777.89 5163.1,4793.84 5163.1,4905.54 5105.69,4962.95 v1@5036.16,4962.95
  Bottom Layer w6: v3(4509.76,4932.49) 4478.09,4900.82 4478.09,4187.99 4620.91,4045.17 4620.91,3524.82 v3(4621.06,3524.68) ; v1@5036.42,4963.3 v1(5036.42,5145.21)
PF9: J2.8 U8.8 | length 1497.7
  Top Layer w6: v1(5110.07,4627.07) 5123.1,4640.09 U8.8@5206.24,4640.09
  Bottom Layer w6: v1(5110.07,4627.07) 5075.63,4592.63 5075.63,3777.27 5133.2,3719.7 5258.68,3719.7 5291.73,3686.65 5291.73,3577.95 5337.93,3531.75 J2.8@5337.93,3427.39
PF10: J2.9 U8.9 | length 1629
  Top Layer w6: v1(5108.82,4598.77) 5130.45,4620.39 U8.9@5206.24,4620.39
  Bottom Layer w6: v1(5108.82,4598.77) 5096.58,4586.52 5096.58,3791.9 5151.56,3736.92 5330.5,3736.92 5389.33,3678.08 5389.33,3375.99 J2.9@5437.93,3327.39
PF11/BOOT0: CN2.4 CN7.4 J1.20 R17.1 R45.2 U8.44 | length 5763.8
  Top Layer w6: R45.2@3335.3,3950.41 3335.3,3918.44 3425.75,3827.99 v2(3425.75,3786.09) 3425.75,3379.85 3561.08,3244.52 3561.08,3176.01 CN7.4@3512.1,3127.03 ; v2(3880.98,4059.92) 3897.47,4076.4 4226.55,4076.4 CN2.4@4277.67,4127.53 4325.08,4127.53 4371.56,4174.01 v1(5415.03,4174.01) ; R17.1@4417.63,5232.49 5339.97,5232.49 v3(5343.97,5228.49) ; v1(5344.04,4937.45) U8.44@5344.04,4836.89 5344.04,4806.67 5414.9,4735.81 v1(5414.9,4591.73)
  Bottom Layer w6: v2(3425.75,3786.09) 3426.02,3785.82 3708.2,3785.82 3746.83,3824.45 3851.6,3824.45 3880.98,3853.84 v2(3880.98,4059.92) ; J1.20@5237.91,5725.49 5237.91,5661.1 5234.44,5657.63 5234.44,5469.51 5344.04,5359.91 v3(5343.97,5228.49) v1(5344.04,4937.45) ; v1(5414.9,4591.73) 5414.9,4174.14 v1(5415.03,4174.01)
PF12: J2.23 U8.23 | length 1689
  Top Layer w6: U8.23@5462.14,4502.29 5462.14,4467.39 5483.04,4446.49 5624.84,4446.49 v1(5624.98,4446.35) ; v3(5814.46,3702) 6072.46,3702 v3(6075.97,3698.49)
  Bottom Layer w6: v1(5624.98,4446.35) 5658.97,4412.36 5658.97,3857.49 v3(5814.46,3702) ; v3(6075.97,3698.49) 6075.97,3471.49 6087.24,3460.22 6087.24,3378.08 J2.23@6137.93,3327.39
PF13: J2.24 U8.24 | length 1596.9
  Top Layer w6: U8.24@5481.84,4502.29 5481.84,4476.65 5494,4464.49 5609.99,4464.49 5615.99,4470.49 5644.33,4470.49 v1(5659.91,4454.92) ; v3(5814.97,3735.49) 6075.97,3735.49 v3(6099.97,3711.49)
  Bottom Layer w6: v1(5659.91,4454.92) 5677.97,4436.85 5677.97,3872.49 v3(5814.97,3735.49) ; v3(6099.97,3711.49) 6099.97,3504.49 6098.97,3503.49 6098.97,3466.35 J2.24@6137.93,3427.39
SWO: CN2.6 CN7.6 R14.2 R52.2 | length 2478
  Top Layer w6: R52.2@3187.92,4182.16 3187.1,4181.33 3187.1,4092.43 3151.16,4056.49 3151.16,3894.58 v1@3320.82,3724.92 ; v1(3320.21,3724.11) 3320.21,3724.31 v1@3320.82,3724.92 ; CN7.6@3412.1,3127.03 3361.98,3177.14 3361.98,3270.73 3321.92,3310.79 3321.92,3723.82 v1@3320.82,3724.92 ; v1(3927.59,3958.11) 3946.18,3976.7 4226.84,3976.7 CN2.6@4277.67,4027.53
  Bottom Layer w6: v1(3320.21,3724.11) 3399.2,3724.11 3411.15,3736.05 3715.25,3736.05 3762.43,3783.23 3888.29,3783.23 3927.59,3822.53 v1(3927.59,3958.11) ; CN2.6@4277.67,4027.53 4278.22,4026.98 R14.2@4413.41,4026.98
USBM: CN6.A7 CN6.B7 R38.1 TP3.2 | length 320.3
  Top Layer w6: CN6.A7@3405.12,5785.52 3405.12,5728.88 ; R38.1@3435.92,5615.48 3435.92,5647.82 v2(3411.92,5671.82) 3405.12,5678.62 3405.12,5728.88 ; CN6.B7@3444.42,5785.52 3444.42,5738.13 3435.17,5728.88 3405.12,5728.88
  Bottom Layer w6: v2(3411.92,5671.82) 3441.93,5671.82 TP3.2@3453.92,5659.82
USBP: CN6.A6 CN6.B6 R37.1 TP3.3 | length 364.9
  Top Layer w6: R37.1@3373.92,5615.48 3391.92,5633.48 v2(3391.92,5651.82) 3391.92,5728.86 3385.42,5735.36 CN6.B6@3385.42,5785.52 3385.92,5786.02 3385.92,5833.82 3395.92,5843.82 3413.92,5843.82 3424.72,5833.02 CN6.A6@3424.72,5785.52
  Bottom Layer w6: TP3.3@3353.92,5659.82 3361.93,5651.82 v2(3391.92,5651.82)
VCC: C8.2 C9.2 C10.2 C11.2 C12.2 C14.2 J9.1 P1.1 R43.1 RP1.1 RP1.2 RP1.3 RP1.4 U6.1 U6.9 U6.24 U6.36 U6.48 U7.5 | length 2731.1
  Top Layer w10: U6.24@3221.25,4457.43 3269.54,4457.43 v1(3269.92,4457.82) ; v2(3338.58,4673.61) 3339.36,4674.39 U6.9@3339.36,4733.03 ; RP1.4@3398.49,4948.58 RP1.3@3398.49,4980.07 RP1.2@3398.49,5011.57 RP1.1@3398.49,5043.06 3398.49,5082.38 3515.92,5199.82 v4(3649.92,5199.82) ; v1(3486.35,4444.77) 3496.84,4434.27 U6.36@3496.84,4398.38 ; U6.1@3496.84,4733.03 3496.84,4692.77 3495.92,4691.85 v2(3495.92,4673.82) 3516.89,4673.82 3517.04,4673.97 U6.48@3555.9,4673.97
  Top Layer w20: v4(3649.92,5199.82) 3648.09,5201.65 C14.2@3648.09,5253.61 3647.58,5254.12 R43.1@3647.58,5321.82 3647.58,5352.57 3655.92,5360.91 U7.5@3655.92,5390.82
  Bottom Layer w10: v1(3486.35,4444.77) 3439.42,4444.77 C11.2@3433.92,4450.26 C10.2@3313.92,4450.26 3277.48,4450.26 v1(3269.92,4457.82) 3269.92,4613.82 3293.48,4637.38 C12.2@3339.92,4637.38 3338.58,4638.72 v2(3338.58,4673.61) 3338.79,4673.82 v2(3495.92,4673.82) C9.2@3495.92,4635.38
  Bottom Layer w15: C9.2@3495.92,4635.38 C8.2@3565.92,4635.38 3612.62,4635.38 3613.92,4634.07 ; P1.1@3655.1,4285.03 3655.1,4394.99 3675.75,4415.65 3675.75,4573.99 3615.67,4634.07 3613.92,4634.07 ; J9.1@3686.1,4754.03 3623.89,4691.82 3621.92,4691.82 3613.92,4683.82 3613.92,4634.07
  Bottom Layer w20: v4(3649.92,5199.82) 3707.92,5141.82 3707.92,4775.85 J9.1@3686.1,4754.03
VCC3.5V: C17.2 D5.2 R50.1 U5.5 | length 223.8
  Top Layer w20: D5.2@3280.67,5171.82 3279.48,5173.01 C17.2@3279.48,5255.82 3281.58,5257.92 R50.1@3281.58,5323.82 3289.92,5332.16 U5.5@3289.92,5390.82
VDD: B2.3 B2.4 C6.2 C7.2 J1.24 J3.8 JP1.1 JP3.2 R13.1 U8.48 | length 4518.6
  Top Layer w6: v3@4401.5,5012.25 4401.74,5012.49 v3(4401.97,5012.49) ; v2(4552.55,3512.19) 4552.55,3467.22 B2.4@4561.2,3458.57 B2.3@4891.91,3458.57
  Top Layer w10: C7.2@5210.73,4929.3 C6.2@5210.73,4985.83 ; C7.2@5210.79,4929.24 5210.79,4916.67 5265.24,4862.22 U8.48@5265.24,4836.89
  Top Layer w20: R13.1@4133.97,4981.99 4145.47,4981.99 4155.97,4992.49 JP3.2@4243.97,4992.49 4296.49,4992.49 4316.25,5012.25 4401.5,5012.25 v4(4578.53,5012.23) 4599,4991.76 5160.68,4991.76 5166.7,4985.74 5210.64,4985.74 C6.2@5210.73,4985.83 ; v4(4578.64,5692.93) 4611.2,5725.49 J1.24@5037.91,5725.49
  Bottom Layer w6: v3(4401.97,5012.49) 4401.97,4180.23 4554.79,4027.41 4554.79,3514.43 v2(4552.55,3512.19)
  Bottom Layer w20: JP3.2@4243.97,4992.49 4244.82,4993.34 JP3.2@4244.82,5013.03 ; JP1.1@4244.82,5130.95 JP3.2@4244.82,5013.03 ; JP3.2@4245.6,5012.26 JP3.2@4244.82,5013.03 ; v4(4578.53,5012.23) 4578.53,5525.21 J3.8@4577.93,5525.82 4577.93,5692.22 v4(4578.64,5692.93)
pads on no net: CN6.A8 CN6.B8 J4.1 J4.8 U6.2 U6.3 U6.4 U6.5 U6.6 U6.14 U6.15 U6.16 U6.17 U6.18 U6.21 U6.22 U6.29 U6.38 U6.41 U6.42 U6.43 U6.45 U6.46

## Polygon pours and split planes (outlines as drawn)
GND on Top Layer (solid, remove dead copper, pour order 0): 3017.5,6117.4 6792.45,6117.4 6792.45,3031.29 3017.5,3031.29
GND on Bottom Layer (solid, remove dead copper, pour order 2): 3000,6103.45 6791.04,6103.45 6791.04,3000 3000,3000

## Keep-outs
Top Layer:
  region: 4077.97,4526.49 4127.97,4526.49 4127.97,4490.49 4077.97,4490.49
  region: 4091.97,4702.49 4121.97,4702.49 4121.97,4670.49 4091.97,4670.49
Bottom Layer:
  region: 6408.77,4097.32 6426.6,4097.32 6426.6,4060.73 6408.77,4060.73
Board Outline Layer:
  circle w1: c6628.35,5962.67 r62.99
  circle w10: c6628.35,5962.67 r62.99
  circle w1: c6628.35,3187.98 r62.99
  circle w10: c6628.35,3187.98 r62.99
  circle w1: c3940.93,3187.98 r62.99
  circle w10: c3940.93,3187.98 r62.99
  circle w1: c4187.27,3626.35 r62.99
  circle w10: c4187.27,3626.35 r62.99
  circle w1: c6237.27,4926.35 r62.99
  circle w10: c6237.27,4926.35 r62.99
  circle w1: c4237.27,5526.35 r62.99
  circle w10: c4237.27,5526.35 r62.99
  circle w1: c3940.94,5962.67 r62.99
  circle w10: c3940.94,5962.67 r62.99
  region: 6469.97,4261.49 6667.97,4261.49 6667.97,3904.49 6469.97,3904.49
  lines w7.99: 3777.67,5691.27 3777.67,6007.93 ; 3777.93,3143.53 3777.93,3593.21 ; 3777.93,3666.27 3777.93,3758.27 ; 3777.93,3869.27 3777.93,4885.27 ; 3777.93,4963.27 3777.93,5613.27 ; 3816.93,3143.47 3816.93,3593.21 ; 3816.93,3666.27 3816.93,3758.27 ; 3816.93,3869.27 3816.93,4885.27 ; 3816.93,4963.27 3816.93,5613.27 ; 3817.19,5691.27 3817.19,6016.48
  lines w8: 3698.93,6086.67 cw(c3698.93,6007.93) 3777.67,6007.93 ; 3699.32,3065.55 ccw(c3699.32,3144.29) 3778.06,3144.29 ; 3777.67,5691.27 3817.19,5691.27 ; 3777.93,3593.21 3816.93,3593.21 ; 3777.93,3666.27 3816.93,3666.27 ; 3777.93,3758.27 3816.93,3758.27 ; 3777.93,3869.27 3816.93,3869.27 ; 3777.93,4885.27 3816.93,4885.27 ; 3777.93,4963.27 3816.93,4963.27 ; 3777.93,5613.27 3816.93,5613.27 ; 3816.88,3144.41 ccw(c3895.84,3144.41) 3895.84,3065.45 ; 3817.19,6007.93 cw(c3895.93,6007.93) 3895.93,6086.67 ; 3049.97,3143.23 ccw(c3128.71,3143.23) 3128.71,3064.49 6711.23,3064.49 ccw(c6711.23,3143.23) 6789.97,3143.23 6789.97,6007.75 ccw(c6711.23,6007.75) 6711.23,6086.49 3128.71,6086.49 ccw(c3128.71,6007.75) 3049.97,6007.75 3049.97,3143.23

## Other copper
Top Layer:
  drawing of 596 lines, arcs and shapes, not listed
Bottom Layer:
  drawing of 345 lines, arcs and shapes, not listed

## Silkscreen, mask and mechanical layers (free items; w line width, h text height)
Top Silkscreen Layer:
  region: 6039.97,5404.49 6019.97,5384.49 6059.97,5384.49
  region: 6119.97,5404.49 6159.97,5404.49 6139.97,5384.49
  lines w6: 3261.92,3350.82 3261.92,3649.82 ; 3361.98,3351.1 3361.98,3649.82 ; 3461.98,3350.79 3461.98,3649.82 ; 3561.98,3350.79 3561.98,3649.82 ; 4107.12,4227.77 4072.95,4261.95 4072.95,4193.36 4107.25,4227.65 ; 4127.67,3979.66 4091.45,3979.66 4091.45,4074.27 4127.67,4074.27
  lines w8: 3362.92,3276.1 3362.92,3315.73 3463.92,3315.73 3463.92,3275.1 ; 3651.92,3343.82 3575.92,3343.82 3614.92,3304.82 3652.92,3342.82
  lines w10: 4749.97,5244.49 6179.97,5244.49 ; 5017.51,3918.99 5470.51,3918.99 ; 5608.94,3919.13 6168.94,3919.13 ; 6245.46,5169.43 6402.94,5169.43 ; 6245.46,5271.1 6402.94,5271.1 ; 6245.46,5369.24 6402.94,5369.24
  text "25" at 6103.87,5996.51 h55.07
  text "47" at 5000.04,5996.11 h55.47
  text "41" at 5310.44,5996.11 h55.47
  text "31" at 5806.59,5996.11 h55.47
  text "A12" at 5715.61,5879.93 h61.63 r45
  text "B8" at 5128.23,5879.32 h61.63 r45
  text "A8" at 5921.77,5878.8 h61.63 r45
  text "B14" at 6019.36,5879.12 h61.63 r45
  text "F6" at 5630.01,5878.43 h61.63 r45
  text "A10" at 5817.99,5877.93 h61.63 r45
  text "B12" at 6119.36,5878.45 h61.63 r45
  text "B7" at 5230.75,5877.32 h61.63 r45
  text "B5" at 5327.8,5877.32 h61.63 r45
  text "B3" at 5425.16,5877.32 h61.63 r45
  text "A14" at 5519.28,5876.6 h61.63 r45
  text "GND" at 5015.63,5872.53 h61.63 r45
  text "GND" at 4079.97,5812.49 h73.96
  text "BOOT0 /  /F11" at 5178.44,5580.74 h43
  text "B4" at 5445.06,5575.84 h61.63 r45
  text "F7" at 5646.15,5574.94 h61.63 r45
  text "B9" at 5137.06,5574.49 h61.63 r45
  text "B6" at 5343.63,5574.49 h61.63 r45
  text "A9" at 5945.3,5573.97 h61.63 r45
  text "B15" at 6040.55,5568.9 h58.55 r45
  text "B13" at 6138.4,5568.9 h58.55 r45
  text "A15" at 5536.19,5568.18 h58.55 r45
  text "A13" at 5737.52,5568.18 h58.55 r45
  text "A11" at 5840.91,5567.71 h61.63 r45
  text "VDD" at 5029.31,5559.51 h59 r45
  text "USART1" at 6343.44,5494.24 h72
  text "4" at 5779.35,5415.97 h73.42 r90
  text "8" at 5318.35,5414.97 h73.42 r90
  text "7" at 5482.35,5414.97 h73.42 r90
  text "2" at 5976.35,5414.97 h73.42 r90
  text "3V3" at 6258.6,5383.71 h72
  text "13" at 4816.64,5375.96 h73.96 r90
  text "12" at 4916.64,5375.96 h73.96 r90
  text "#6" at 5578.64,5369.96 h73.96 r90
  text "#5" at 5679.64,5369.96 h73.96 r90
  text "#9" at 5217.64,5368.96 h73.96 r90
  text "#3" at 5878.64,5368.96 h73.96 r90
  text "#11" at 5016.64,5331.07 h73.96 r90
  text "#10" at 5117.64,5331.07 h73.96 r90
  text "SCL" at 4416.64,5321.07 h73.96 r90
  text "SDA" at 4516.64,5321.07 h73.96 r90
  text "GND" at 4717.35,5321.07 h73.96 r90
  text "TX" at 6283.4,5282.56 h72
  text "GND" at 4007.97,5280.49 h74
  text "TX 1" at 6079.64,5278.17 h73.96 r90
  text "RX 0" at 6180.64,5278.17 h73.96 r90
  text "VDDA" at 4617.35,5276.17 h73.96 r90
  text "DIGITAL(#=PWM)" at 5177.51,5256.55 h73.96
  text "LD:" at 3680.94,5227.86 h55.47 r270
  text "BOOT0" at 3943.46,5185.41 h73.96
  text "RX" at 6283.4,5181.76 h72
  text "1" at 3683.33,5114.63 h55.07 r270
  text "VDD" at 4009.97,5096.49 h74
  text "AT-Link-EZ V1.4" at 3073.16,5092.28 h90 r270
  text "GND" at 6259.6,5081.64 h72
  text "2" at 3682.33,5047.63 h55.07 r270
  text "3" at 3681.33,4974.63 h55.07 r270
  text "IDD" at 4323.97,4910.49 h73.96
  text "4" at 3682.33,4899.63 h55.07 r270
  text "5V" at 6329.62,4687.66 h73.96
  text "MISO" at 5910.84,4684.48 h73.96
  text "MOSI" at 6334.38,4587.45 h73.96
  text "SCK" at 5913.3,4585.9 h73.96
  text "RESET" at 5862.14,4487.32 h73.96
  text "GND" at 6331.73,4487.23 h73.96
  text "NSS" at 5915.23,4388.73 h73.96
  text "PB11" at 6333.84,4387.56 h73.96
  text "CAN1" at 6512.97,4310.49 h73.96
  text "AT-Link" at 4104.97,4289.49 h74
  text "3V3" at 3904.86,4184.27 h72
  text "E5V" at 4348.86,4182.27 h72
  text "H" at 6783.4,4146.02 h73.96 r90
  text "BOOT0" at 4348.86,4088.27 h72
  text "SWDIO" at 3858.06,4084.27 h72
  text "AT-START-M416 V1.1" at 4605.08,4012.49 h110
  text "SWCLK" at 3835.26,3990.27 h72
  text "SWO" at 4348.86,3984.27 h72
  text "L" at 6783.4,3982.12 h73.96 r90
  text "NRST" at 3894.86,3890.27 h72
  text "USART1_RX" at 4348.86,3884.27 h72
  text "POWER" at 5249.11,3838.17 h73.96
  text "ANALOG IN" at 5773.69,3837.72 h73.96
  text "GND" at 3942.86,3786.27 h72
  text "USART1_TX" at 4348.86,3784.27 h72
  text "IOREF" at 4879.34,3709.13 h73.96 r90
  text "RESET" at 4979.34,3709.13 h73.96 r90
  text "3.3V" at 5077.35,3707.17 h73.96 r90
  text "VIN" at 5481.34,3704.92 h73.96 r90
  text "AN0" at 5674.34,3704.92 h73.96 r90
  text "AN1" at 5774.34,3704.92 h73.96 r90
  text "AN2" at 5875.35,3705.07 h73.96 r90
  text "AN3" at 5974.34,3704.92 h73.96 r90
  text "AN4" at 6074.34,3704.92 h73.96 r90
  text "AN5" at 6174.34,3704.92 h73.96 r90
  text "5V" at 5177.35,3702.96 h73.96 r90
  text "GND" at 5284.34,3697.92 h73.96 r90
  text "GND" at 5386.34,3697.92 h73.96 r90
  text "120Ω" at 6778.97,3667.49 h73.96 r90
  text "SWC" at 3371.87,3642.24 h64.72 r270
  text "GND" at 3180.56,3641.23 h64.72 r270
  text "SWD" at 3470.49,3641.1 h64.72 r270
  text "3V3" at 3577.12,3640.09 h64.72 r270
  text "NRST" at 3278.56,3636.39 h64.72 r270
  text "F1*" at 5225.63,3486.37 h54 r45
  text "B0" at 5831.08,3484.65 h61.63 r45
  text "F9" at 5332.07,3484.07 h61.63 r45
  text "B2" at 5928.11,3482.65 h61.63 r45
  text "A4" at 5622.52,3480.81 h61.63 r45
  text "A6" at 5723.12,3481.46 h61.63 r45
  text "BOOT0" at 3472.39,3479.76 h58 r270
  text "A0" at 5421.39,3480.13 h61.63 r45
  text "A2" at 5522.89,3480.13 h61.63 r45
  text "B11" at 6023.8,3477.72 h61.63 r45
  text "F13" at 6118.02,3474 h61.63 r45
  text "GND" at 6331.97,3474.49 h73.96
  text "C13" at 5016.78,3472.5 h58.55 r45
  text "C15*" at 5113.07,3472.5 h54 r45
  text "E5V" at 3575.06,3470.68 h64.72 r270
  text "SWO" at 3377.61,3466.8 h64.72 r270
  text "RX" at 3179.67,3455.67 h64.72 r270
  text "TX" at 3278.56,3455.7 h64.72 r270
  text "B1" at 5946.08,3177.81 h61.63 r45
  text "A1" at 5542.66,3175.33 h61.63 r45
  text "F8" at 5046.53,3171.66 h61.63 r45
  text "F10" at 5443.38,3170.38 h61.63 r45
  text "A5" at 5747.4,3166.71 h61.63 r45
  text "A3" at 5642.84,3165.5 h61.63 r45
  text "F0*" at 5221.45,3163.76 h54 r45
  text "A7" at 5846.02,3164.23 h61.63 r45
  text "B10" at 6041.77,3164.44 h55.47 r45
  text "C14*" at 5127.53,3162.12 h54 r45
  text "NRST /  /F2" at 5285.51,3157.74 h50
  text "PF12" at 6142.01,3154.54 h55.47 r45
  text "USER" at 4636.7,3143.17 h73.96
  text "RESET" at 4164.54,3142.45 h73.96
  text "1" at 5032.37,3095.66 h55.47
  text "11" at 5521.33,3095.66 h55.47
  text "21" at 6015.45,3095.66 h55.47
  text "23" at 6111.37,3095.66 h55.47
Bottom Silkscreen Layer:
  text "31" at 5840.45,5872.12 h60 r315
  text "29" at 5948.11,5871.48 h60 r315
  text "39" at 5443.44,5869.68 h60 r315
  text "25" at 6146.66,5869.71 h60 r315
  text "41" at 5340.54,5869.15 h60 r315
  text "27" at 6046.13,5868.55 h60 r315
  text "35" at 5648.38,5867.91 h60 r315
  text "37" at 5545.65,5866.74 h60 r315
  text "33" at 5749.1,5867.34 h60 r315
  text "45" at 5145.75,5864.94 h60 r315
  text "47" at 5048.66,5863.77 h60 r315
  text "43" at 5248.83,5864.37 h60 r315
  text "42" at 5338.67,5594.37 h60 r315
  text "48" at 5035.67,5593.37 h60 r315
  text "46" at 5136.67,5593.37 h60 r315
  text "44" at 5235.67,5593.37 h60 r315
  text "40" at 5437.67,5593.37 h60 r315
  text "38" at 5533.67,5593.37 h60 r315
  text "36" at 5633.67,5593.37 h60 r315
  text "34" at 5734.67,5593.37 h60 r315
  text "32" at 5836.67,5593.37 h60 r315
  text "30" at 5935.67,5593.37 h60 r315
  text "28" at 6036.67,5593.37 h60 r315
  text "26" at 6139.67,5593.37 h60 r315
  text "VDD" at 3716.4,4911.56 h55.47 r90
  text "VDD" at 3589,4252.33 h55.47
  text "AT32M416CBT7" at 5703.97,4214.14 h184.9
  text "M-SWDIO" at 3584.22,4154.43 h55.47
  text "M-SWCLK" at 3584.22,4054.43 h55.47
  text "M-NRST" at 3585.8,3954.43 h55.47
  text "GND" at 3590.55,3854.43 h55.47
  text "2" at 5029.36,3478.96 h60 r315
  text "6" at 5229.36,3476.55 h60 r315
  text "8" at 5329.58,3476.55 h60 r315
  text "4" at 5133.36,3474.82 h60 r315
  text "10" at 5435.58,3468.03 h60 r315
  text "12" at 5538.58,3468.03 h60 r315
  text "14" at 5639.58,3468.07 h60 r315
  text "16" at 5741.58,3468.03 h60 r315
  text "24" at 6145.58,3467.66 h60 r315
  text "18" at 5838.58,3467.43 h60 r315
  text "20" at 5941.58,3465.63 h60 r315
  text "22" at 6043.58,3465.63 h60 r315
  text "1" at 5017.73,3217.67 h60 r315
  text "9" at 5423.91,3216.54 h60 r315
  text "5" at 5227.85,3214.91 h60 r315
  text "3" at 5124.24,3214.38 h60 r315
  text "7" at 5322.48,3213.25 h60 r315
  text "11" at 5526.57,3210.17 h60 r315
  text "19" at 5929.57,3208.02 h60 r315
  text "13" at 5627.57,3205.83 h60 r315
  text "15" at 5732.57,3206.36 h60 r315
  text "17" at 5830.57,3205.26 h60 r315
  text "21" at 6032.57,3203.98 h60 r315
  text "23" at 6132.57,3197.63 h60 r315
Mechanical Layer:
  circle w1: c6628.35,5962.67 r62.99
  circle w1: c6628.35,3187.98 r62.99
  circle w1: c3940.93,3187.98 r62.99
  circle w1: c4187.27,3626.35 r62.99
  circle w1: c6237.27,4926.35 r62.99
  circle w1: c4237.27,5526.35 r62.99
  circle w1: c3940.94,5962.67 r62.99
